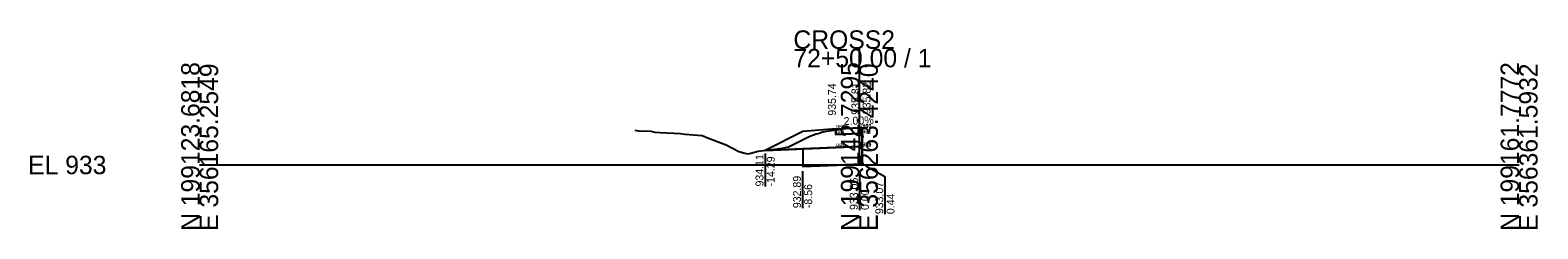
# Model space of a CAD drawing. Extents: x -26 to 203, y -10 to 14021.
# Drawn here: x -25.7 to 202.8, y 13490.3 to 13520.5 of the extents above; entities that cross this region are included whole.
import ezdxf

# ---------------------------------------------------------------- set-up
doc = ezdxf.new("R2010")
doc.units = 0
for name, color, linetype in [('Default', 7, 'Continuous'), ('P_E_XS_Ground', 7, 'Continuous'), ('P_XS', 7, 'Continuous'), ('P_XS_Bold', 7, 'Continuous'), ('P_XS_EAR_CommonGrnd', 7, 'Continuous'), ('P_XS_Lane', 7, 'Continuous'), ('P_XS_Rock', 7, 'Continuous')]:
    doc.layers.add(name, color=color, linetype=linetype)

msp = doc.modelspace()

# ---------------------------------------------------------------- linework, layer by layer
at = {"layer": 'Default'}
for p, q in [((100, 13500), (100, 13517.62)), ((0, 13500), (100, 13500)), ((100, 13500), (200, 13500))]:
    msp.add_line(p, q, dxfattribs=at)
at = {"layer": 'P_E_XS_Ground'}
for p, q in [((65.97, 13505.27), (66.53, 13505.18)), ((66.53, 13505.18), (68.37, 13505.12)), ((68.37, 13505.12), (68.99, 13504.99)), ((68.99, 13504.99), (69.81, 13504.93)), ((69.81, 13504.93), (72.87, 13504.76)), ((72.87, 13504.76), (73.52, 13504.7)), ((73.52, 13504.7), (76.19, 13504.45)), ((76.19, 13504.45), (77.11, 13504.08)), ((77.11, 13504.08), (79.38, 13503.23)), ((89.24, 13502.75), (92.41, 13504.3)), ((92.41, 13504.3), (93.46, 13504.72)), ((93.46, 13504.72), (93.76, 13504.8)), ((93.76, 13504.8), (94.46, 13505.04)), ((94.46, 13505.04), (95.08, 13505.12)), ((95.08, 13505.12), (97.87, 13505.51)), ((97.87, 13505.51), (98.28, 13505.61)), ((98.28, 13505.61), (100, 13505.63)), ((100, 13505.63), (100.58, 13505.64)), ((79.38, 13503.23), (79.79, 13503.07)), ((79.79, 13503.07), (81.71, 13502.04)), ((81.71, 13502.04), (82.66, 13501.81)), ((82.66, 13501.81), (83.12, 13501.71)), ((83.12, 13501.71), (83.53, 13501.78)), ((83.53, 13501.78), (84.67, 13502.08)), ((84.67, 13502.08), (88.33, 13502.56)), ((88.33, 13502.56), (89.24, 13502.75))]:
    msp.add_line(p, q, dxfattribs=at)
at = {"layer": 'P_XS'}
for p, q in [((96.44, 13505.48), (96.44, 13504.64)), ((96.44, 13504.64), (100, 13504.79)), ((100.44, 13504.8), (100, 13504.79)), ((100.44, 13504.8), (100.44, 13505.64)), ((100.44, 13502.8), (100.44, 13504.8)), ((85.71, 13502.21), (100, 13502.79)), ((91.44, 13502.44), (91.44, 13499.77)), ((100.44, 13502.8), (100, 13502.79)), ((100.44, 13502.8), (100.44, 13500.13)), ((100.44, 13500.13), (91.44, 13499.77))]:
    msp.add_line(p, q, dxfattribs=at)
at = {"layer": 'P_XS_EAR_CommonGrnd'}
for points in [[(96.44, 13505.48), (91.44, 13505.08), (85.71, 13502.21), (88.33, 13502.56), (89.24, 13502.75), (92.41, 13504.3), (93.46, 13504.72), (93.76, 13504.8), (94.46, 13505.04), (95.08, 13505.12), (96.44, 13505.31)], [(85.71, 13502.21), (88.33, 13502.56), (89.24, 13502.75), (92.41, 13504.3), (93.46, 13504.72), (93.76, 13504.8), (94.46, 13505.04), (95.08, 13505.12), (96.44, 13505.31), (96.44, 13504.64), (100, 13504.79), (100.44, 13504.8), (100.44, 13502.8), (100, 13502.79), (91.44, 13502.44)], [(97.98, 13505.54), (100, 13505.62), (100.44, 13505.64), (100.44, 13504.8), (100, 13504.79), (96.44, 13504.64), (96.44, 13505.31), (97.87, 13505.51)], [(96.44, 13505.48), (97.98, 13505.54), (97.87, 13505.51), (96.44, 13505.31)], [(98.28, 13505.61), (100, 13505.62), (97.98, 13505.54)], [(100.44, 13502.8), (100, 13502.79), (91.44, 13502.44), (91.44, 13499.77), (100.44, 13500.13)]]:
    msp.add_lwpolyline(points, close=True, dxfattribs=at)
at = {"layer": 'P_XS_Lane'}
for p, q in [((91.44, 13505.08), (85.71, 13502.21)), ((96.44, 13505.48), (91.44, 13505.08)), ((96.44, 13505.48), (100, 13505.62)), ((100, 13505.62), (100.44, 13505.64))]:
    msp.add_line(p, q, dxfattribs=at)
at = {"layer": 'P_XS_Rock'}
for p, q in [((85.71, 13501.73), (85.71, 13496.73)), ((100.98, 13499.87), (103.87, 13498.23)), ((91.39, 13499.04), (91.39, 13493.45)), ((100, 13498.86), (100, 13493.17)), ((103.87, 13498.23), (103.87, 13492.54))]:
    msp.add_line(p, q, dxfattribs=at)

# ---------------------------------------------------------------- texts
at = {"layer": 'Default'}
for s, p in [('CROSS2', (90, 13517.62)), ('72+50.00 / 1', (90, 13514.82)), ('EL 933', (-26, 13498.6))]:
    msp.add_text(s, height=2.8, dxfattribs=at).set_placement(p)
for s, p in [('N 199123.6818', (0, 13490)), ('N 199142.7295', (100, 13490)), ('N 199161.7772', (200, 13490)), ('E 356165.2549', (2.8, 13490)), ('E 356263.4240', (102.8, 13490)), ('E 356361.5932', (202.8, 13490))]:
    msp.add_text(s, height=2.8, rotation=90, dxfattribs=at).set_placement(p)
at = {"layer": 'P_XS_Bold'}
for s, p in [('951', (96.44, 13505.48)), ('9', (96.44, 13505.48)), ('900', (96.44, 13505.48)), ('961', (96.44, 13504.64)), ('952', (100, 13505.62)), ('952', (100, 13505.62)), ('962', (100, 13504.79)), ('962', (100, 13504.79)), ('951', (100.44, 13505.64)), ('9', (100.44, 13505.64)), ('900', (100.44, 13505.64)), ('910', (100.44, 13505.64)), ('961', (100.44, 13504.8)), ('971', (96.44, 13502.64)), ('998', (96.44, 13502.64)), ('972', (100, 13502.79)), ('972', (100, 13502.79)), ('540', (100.44, 13502.8)), ('971', (100.44, 13502.8)), ('998', (100.44, 13502.8))]:
    msp.add_text(s, height=0.6, dxfattribs=at).set_placement(p)
at = {"layer": 'P_XS_Rock'}
for s, rotation, p in [('935.74', 90, (96.44, 13507.48)), ('935.81', 90, (100, 13507.62)), ('935.81', 90, (100, 13507.62)), ('935.81', 90, (100, 13507.62)), ('935.81', 90, (100, 13507.62)), ('935.82', 90, (101.69, 13507.7)), ('2.00%', 2.2906, (97.64, 13506.05)), ('934.11', 90, (85.46, 13496.74)), ('-14.29', 90, (87.16, 13496.74)), ('932.89', 90, (91.14, 13493.45)), ('933.06', 90, (99.75, 13493.17)), ('933.07', 90, (103.62, 13492.54)), ('-8.56', 90, (92.84, 13493.45)), ('0.00', 90, (101.45, 13493.17)), ('0.44', 90, (105.32, 13492.54))]:
    msp.add_text(s, height=1.2, rotation=rotation, dxfattribs=at).set_placement(p)

doc.saveas('drawing.dxf')
